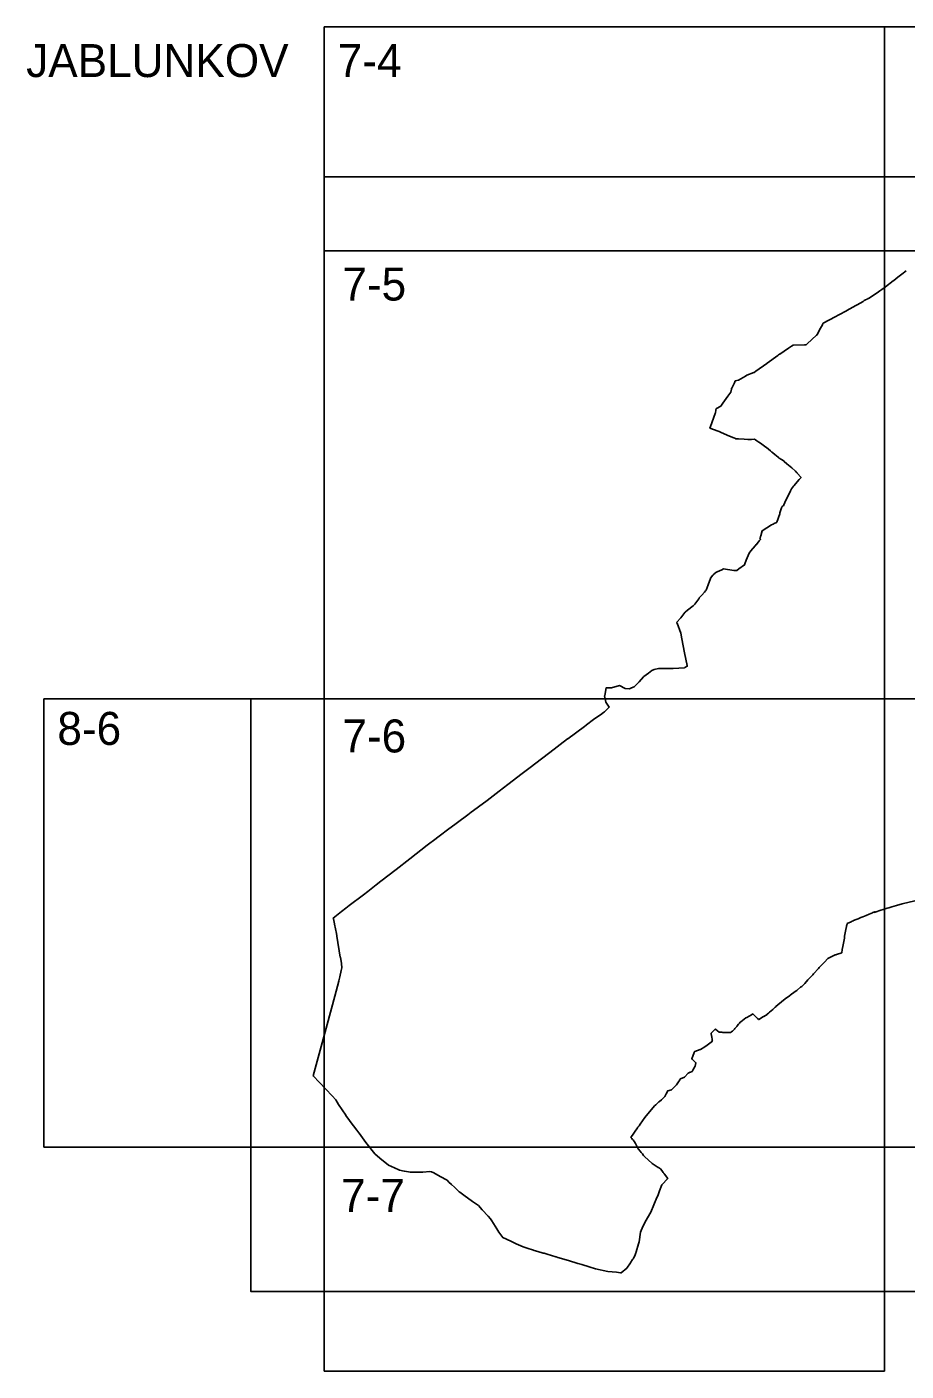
# Model space of a CAD drawing. Extents: x -447352 to -425530, y -1135906 to -1125104.
# Drawn here: x -438504.6 to -438259.4, y -1126653.4 to -1126278.4 of the extents above; entities that cross this region are included whole.
import ezdxf

# ---------------------------------------------------------------- set-up
doc = ezdxf.new("R2010")
doc.units = 0
for name, color, linetype in [('Vrstva 1', 7, 'Continuous'), ('Vrstva 10', 7, 'Continuous'), ('Vrstva 4', 7, 'Continuous')]:
    doc.layers.add(name, color=color, linetype=linetype)

msp = doc.modelspace()

# ---------------------------------------------------------------- linework, layer by layer
at = {"layer": 'Vrstva 1'}
for points in [[(-438259.36, -1126346.44), (-438260.57, -1126347.4), (-438260.57, -1126347.4), (-438261.72, -1126348.27), (-438262.29, -1126348.7), (-438262.87, -1126349.14), (-438263.03, -1126349.26), (-438265.16, -1126350.9), (-438266.23, -1126351.72), (-438266.7, -1126352.06), (-438267.46, -1126352.57), (-438267.71, -1126352.73), (-438268.3, -1126353.12), (-438268.34, -1126353.15), (-438268.55, -1126353.29), (-438269.46, -1126353.89), (-438269.47, -1126353.89), (-438269.94, -1126354.15), (-438270.09, -1126354.23), (-438270.27, -1126354.33), (-438270.73, -1126354.58), (-438270.91, -1126354.69), (-438271.07, -1126354.78), (-438271.17, -1126354.84), (-438271.41, -1126354.98), (-438273.07, -1126355.92), (-438273.24, -1126356.01), (-438273.47, -1126356.14), (-438275.94, -1126357.54), (-438276.06, -1126357.61), (-438278.17, -1126358.74), (-438279.19, -1126359.29), (-438282.53, -1126361.1), (-438282.7, -1126361.4), (-438282.76, -1126361.51), (-438283.54, -1126362.97), (-438284.22, -1126364.29), (-438284.36, -1126364.42), (-438284.45, -1126364.5), (-438285.59, -1126365.54), (-438287.1, -1126366.92), (-438287.27, -1126367.07), (-438287.27, -1126367.08), (-438287.74, -1126367.09), (-438290.93, -1126367.18), (-438290.94, -1126367.18), (-438291.37, -1126367.47), (-438292.2, -1126368.04), (-438294.67, -1126369.7), (-438294.71, -1126369.72), (-438294.95, -1126369.9), (-438295.22, -1126370.1), (-438298.2, -1126372.23), (-438298.27, -1126372.28), (-438301.27, -1126374.46), (-438301.74, -1126374.8), (-438301.9, -1126374.86), (-438303.84, -1126375.58), (-438303.85, -1126375.58), (-438304.24, -1126375.82), (-438306.12, -1126376.98), (-438307.04, -1126377.19), (-438307.29, -1126377.7), (-438308.05, -1126379.21), (-438308.06, -1126379.22), (-438308.13, -1126379.48), (-438308.33, -1126380.32), (-438309.16, -1126381.43), (-438310.53, -1126383.38), (-438311.09, -1126384.19), (-438311.12, -1126384.21), (-438312.28, -1126384.85), (-438312.38, -1126384.91), (-438312.45, -1126385.3), (-438312.6, -1126386.11), (-438312.65, -1126386.3), (-438313.94, -1126389.88), (-438314.11, -1126390.36), (-438314.08, -1126390.35), (-438314.06, -1126390.34), (-438313.38, -1126390.6), (-438311.57, -1126391.26), (-438310.95, -1126391.55), (-438308.66, -1126392.63), (-438308.64, -1126392.63), (-438307.48, -1126393.1), (-438307.01, -1126393.28), (-438306.98, -1126393.29), (-438306.55, -1126393.32), (-438306.41, -1126393.33), (-438306.19, -1126393.35), (-438304.59, -1126393.45), (-438303.55, -1126393.52), (-438302.5, -1126393.49), (-438301.66, -1126393.46), (-438301.65, -1126393.46), (-438301.37, -1126393.61), (-438301, -1126393.87), (-438300.45, -1126394.25), (-438300.06, -1126394.53), (-438298.5, -1126395.67), (-438298.33, -1126395.79), (-438297.22, -1126396.71), (-438296.83, -1126397.03), (-438296.65, -1126397.18), (-438295.9, -1126397.79), (-438295.63, -1126398.02), (-438295.03, -1126398.51), (-438294.81, -1126398.69), (-438294.17, -1126399.11), (-438293.42, -1126399.61), (-438293.39, -1126399.63), (-438292.63, -1126400.31), (-438291.75, -1126401.09), (-438291.31, -1126401.47), (-438290.3, -1126402.36), (-438290.04, -1126402.59), (-438289.99, -1126402.64), (-438289.89, -1126402.74), (-438289.88, -1126402.75), (-438289.79, -1126402.85), (-438289.76, -1126402.88), (-438288.71, -1126404.11), (-438288.72, -1126404.12), (-438289.16, -1126404.61), (-438289.22, -1126404.68), (-438289.79, -1126405.31), (-438290.61, -1126406.37), (-438290.78, -1126406.58), (-438291.34, -1126407.3), (-438291.64, -1126407.83), (-438291.66, -1126407.87), (-438291.67, -1126407.89), (-438291.8, -1126408.17), (-438292.6, -1126409.84), (-438292.91, -1126410.48), (-438293.53, -1126411.77), (-438293.64, -1126412.01), (-438293.65, -1126412.01), (-438293.69, -1126412.04), (-438293.98, -1126412.24), (-438294.06, -1126412.28), (-438294.11, -1126412.38), (-438294.2, -1126412.58), (-438294.29, -1126412.86), (-438294.46, -1126413.42), (-438294.47, -1126413.44), (-438294.59, -1126413.94), (-438294.61, -1126414.01), (-438294.6, -1126414.07), (-438294.59, -1126414.15), (-438294.59, -1126414.22), (-438294.6, -1126414.27), (-438295.48, -1126416.6), (-438295.5, -1126416.65), (-438295.52, -1126416.69), (-438295.53, -1126416.7), (-438296.23, -1126417), (-438296.48, -1126417.11), (-438296.95, -1126417.35), (-438299.56, -1126419.04), (-438299.56, -1126419.04), (-438299.93, -1126420.35), (-438300.01, -1126420.61), (-438300.12, -1126421.03), (-438300.18, -1126421.24), (-438300.18, -1126421.25), (-438300.17, -1126421.25), (-438300, -1126421.41), (-438300.01, -1126421.42), (-438300.37, -1126421.81), (-438301.17, -1126422.81), (-438301.18, -1126422.82), (-438301.39, -1126423.07), (-438301.39, -1126423.08), (-438301.51, -1126423.23), (-438302.67, -1126424.58), (-438303.21, -1126425.21), (-438303.97, -1126427.16), (-438304.35, -1126428.18), (-438304.48, -1126428.53), (-438306.01, -1126429.63), (-438306.63, -1126430.07), (-438306.81, -1126430.11), (-438306.83, -1126430.11), (-438307.46, -1126430.02), (-438310.3, -1126429.6), (-438310.79, -1126429.84), (-438312.12, -1126430.48), (-438312.66, -1126430.74), (-438312.69, -1126430.77), (-438313.12, -1126431.18), (-438313.29, -1126431.4), (-438313.95, -1126432.25), (-438313.95, -1126432.26), (-438314.62, -1126434.06), (-438315.19, -1126435.56), (-438315.19, -1126435.56), (-438315.33, -1126435.78), (-438315.66, -1126436.15), (-438316.38, -1126436.95), (-438317.08, -1126437.72), (-438317.09, -1126437.74), (-438317.22, -1126437.93), (-438318.29, -1126439.5), (-438318.76, -1126439.88), (-438320.33, -1126441.14), (-438321, -1126441.68), (-438321.1, -1126441.76), (-438321.13, -1126441.8), (-438322.25, -1126443.23), (-438323.39, -1126444.54), (-438323.24, -1126444.71), (-438323.23, -1126444.74), (-438323.23, -1126444.75), (-438322.22, -1126447.51), (-438321.94, -1126449.17), (-438321.62, -1126451.12), (-438321.21, -1126453.08), (-438320.48, -1126456.58), (-438320.44, -1126456.78), (-438321.09, -1126457.12), (-438321.21, -1126457.19), (-438324.38, -1126457.45), (-438324.54, -1126457.45), (-438326.03, -1126457.42), (-438328.42, -1126457.4), (-438329.7, -1126457.67), (-438330.3, -1126457.94), (-438331.28, -1126458.74), (-438332.58, -1126459.61), (-438332.67, -1126459.72), (-438333.83, -1126461.14), (-438335.28, -1126462.48), (-438335.97, -1126462.8), (-438336.57, -1126463.08), (-438337.74, -1126463.01), (-438339.35, -1126462.16), (-438341.59, -1126462.83), (-438343.07, -1126462.8), (-438343.45, -1126464.91), (-438343.46, -1126464.93), (-438343.47, -1126465.02), (-438343.18, -1126466.83), (-438342.21, -1126468.15), (-438342.2, -1126468.17), (-438342.94, -1126468.92), (-438343.55, -1126469.48), (-438343.8, -1126469.71), (-438344.6, -1126470.34), (-438346.53, -1126471.57), (-438346.59, -1126471.61), (-438348.56, -1126473.14), (-438348.62, -1126473.18), (-438349.11, -1126473.56), (-438353.77, -1126477.02), (-438353.8, -1126477.05), (-438358.75, -1126480.81), (-438363.01, -1126484.06), (-438363.89, -1126484.72), (-438366.46, -1126486.66), (-438370.46, -1126489.79), (-438372.9, -1126491.66), (-438376.21, -1126494.19), (-438376.26, -1126494.23), (-438381.05, -1126497.74), (-438381.28, -1126497.92), (-438384.89, -1126500.6), (-438387.28, -1126502.42), (-438389.25, -1126503.9), (-438391.57, -1126505.65), (-438391.8, -1126505.82), (-438392.93, -1126506.71), (-438397.75, -1126510.51), (-438401.64, -1126513.46), (-438405.86, -1126516.71), (-438407.15, -1126517.71), (-438409.54, -1126519.59), (-438410.72, -1126520.51), (-438414.66, -1126523.56), (-438415.59, -1126524.27), (-438416.83, -1126525.23), (-438419.15, -1126527.03), (-438419.15, -1126527.03), (-438419.11, -1126527.21), (-438418.82, -1126528.59), (-438418.79, -1126528.75), (-438418.26, -1126531.29), (-438418.1, -1126532.02), (-438418.1, -1126532.06), (-438417.17, -1126537.94), (-438417.16, -1126537.97), (-438416.86, -1126539.7), (-438416.86, -1126539.72), (-438416.8, -1126540.09), (-438416.74, -1126540.51), (-438416.77, -1126540.88), (-438416.92, -1126541.61), (-438417.3, -1126543.4), (-438417.59, -1126544.58), (-438417.61, -1126544.63), (-438418.72, -1126548.8), (-438420.82, -1126556.68), (-438422.81, -1126563.9), (-438424.74, -1126571), (-438424.75, -1126571.04), (-438419.47, -1126576.64), (-438418.42, -1126577.77), (-438417.66, -1126578.99), (-438415.64, -1126582.05), (-438415.59, -1126582.12), (-438414.58, -1126583.53), (-438414.42, -1126583.74), (-438412.54, -1126586.22), (-438411.97, -1126586.96), (-438411.94, -1126587), (-438411.42, -1126587.72), (-438410.04, -1126589.62), (-438409.71, -1126590.07), (-438407.56, -1126592.79), (-438406.16, -1126594.01), (-438403.76, -1126595.99), (-438402.02, -1126596.74), (-438400.83, -1126597.26), (-438400.7, -1126597.31), (-438399.37, -1126597.59), (-438399.23, -1126597.62), (-438397.61, -1126597.95), (-438397.58, -1126597.95), (-438396.62, -1126597.93), (-438396.24, -1126597.93), (-438395.72, -1126597.92), (-438395.04, -1126597.91), (-438394.13, -1126597.87), (-438392.18, -1126597.71), (-438391.73, -1126597.78), (-438391.07, -1126598.13), (-438389.35, -1126599.08), (-438387.39, -1126600.18), (-438386.87, -1126600.66), (-438386.15, -1126601.34), (-438385.35, -1126602.09), (-438384.03, -1126603.39), (-438383.89, -1126603.49), (-438382.7, -1126604.34), (-438380.29, -1126606.05), (-438378.65, -1126607.23), (-438377.6, -1126608.41), (-438375.96, -1126610.23), (-438375.32, -1126610.94), (-438374.96, -1126611.53), (-438374.5, -1126612.27), (-438373.56, -1126613.74), (-438372.93, -1126614.66), (-438371.89, -1126616.1), (-438370.82, -1126616.61), (-438369.44, -1126617.26), (-438368.13, -1126617.87), (-438366.16, -1126618.76), (-438365.03, -1126619.11), (-438363.31, -1126619.68), (-438363.16, -1126619.73), (-438362.07, -1126620.05), (-438360.65, -1126620.47), (-438360.64, -1126620.47), (-438360.43, -1126620.53), (-438360.37, -1126620.55), (-438359.51, -1126620.81), (-438357.12, -1126621.5), (-438357, -1126621.54), (-438356.52, -1126621.68), (-438353.59, -1126622.55), (-438350.9, -1126623.38), (-438350.56, -1126623.48), (-438349.8, -1126623.71), (-438347.79, -1126624.33), (-438346.06, -1126624.88), (-438342.6, -1126625.62)], [(-438342.6, -1126625.62), (-438340.21, -1126625.81), (-438339.01, -1126626.04), (-438338.9, -1126625.95), (-438337.32, -1126624.68), (-438336.29, -1126623.2), (-438336.18, -1126623.05), (-438335.66, -1126622.29), (-438335.55, -1126622.12), (-438335.41, -1126621.89), (-438335.03, -1126621.26), (-438334.76, -1126620.43), (-438334.74, -1126620.36), (-438334.72, -1126620.31), (-438334.69, -1126620.2), (-438334.66, -1126620.11), (-438334.66, -1126620.1), (-438334.03, -1126617.9), (-438333.89, -1126617.38), (-438333.44, -1126614.63), (-438333.44, -1126614.63), (-438333.25, -1126614.19), (-438332.99, -1126613.57), (-438332.2, -1126611.74), (-438330.63, -1126609.09), (-438328.88, -1126604.96), (-438328.56, -1126604.32), (-438328.52, -1126604.19), (-438328.13, -1126603.09), (-438327.54, -1126601.42), (-438325.86, -1126599.71), (-438326.79, -1126598.47), (-438326.85, -1126598.38), (-438326.9, -1126598.32), (-438326.93, -1126598.28), (-438327, -1126598.18), (-438327.05, -1126598.1), (-438327.13, -1126597.98), (-438327.49, -1126597.46), (-438327.86, -1126597), (-438328.43, -1126596.63), (-438328.53, -1126596.57), (-438330.18, -1126595.5), (-438332.37, -1126593.56), (-438332.5, -1126593.39), (-438332.53, -1126593.35), (-438332.61, -1126593.25), (-438332.95, -1126592.83), (-438333.28, -1126592.42), (-438333.54, -1126592.1), (-438334.02, -1126591.51), (-438334.1, -1126591.41), (-438334.6, -1126590.45), (-438334.89, -1126589.89), (-438335.12, -1126589.46), (-438335.17, -1126589.37), (-438335.21, -1126589.32), (-438335.47, -1126589.03), (-438335.67, -1126588.8), (-438335.93, -1126588.51), (-438336.15, -1126588.26), (-438334.29, -1126585.52), (-438334.2, -1126585.4), (-438333.88, -1126584.95), (-438333.56, -1126584.51), (-438332.23, -1126582.68), (-438329.55, -1126579.42), (-438329.2, -1126579.1), (-438328.49, -1126578.4), (-438328.38, -1126578.31), (-438328.19, -1126578.17), (-438327.59, -1126577.69), (-438326.73, -1126576.85), (-438326.32, -1126576.09), (-438325.85, -1126575.22), (-438324.8, -1126574.98), (-438323.4, -1126573.55), (-438322.86, -1126572.7), (-438322.85, -1126572.69), (-438322.85, -1126572.67), (-438322.64, -1126572.34), (-438322.59, -1126572.26), (-438322.35, -1126571.87), (-438321.19, -1126571.43), (-438320.17, -1126570.25), (-438319.64, -1126570.05), (-438319.52, -1126570), (-438319.1, -1126569.84), (-438318.88, -1126569.45), (-438318.83, -1126569.36), (-438318.66, -1126569.06), (-438318.25, -1126568.32), (-438318.05, -1126567.41), (-438318.05, -1126567.39), (-438318.04, -1126567.38), (-438319.09, -1126566.39), (-438319.11, -1126566.38), (-438319.12, -1126566.36), (-438319.17, -1126566.32), (-438318.52, -1126564.52), (-438318.45, -1126564.32), (-438318.29, -1126564.26), (-438317.56, -1126563.97), (-438316.87, -1126563.7), (-438316.75, -1126563.65), (-438315.54, -1126562.94), (-438315.42, -1126562.86), (-438315.42, -1126562.86), (-438315.41, -1126562.85), (-438315.29, -1126562.78), (-438313.43, -1126561.38), (-438313.43, -1126561.34), (-438313.46, -1126561.18), (-438313.53, -1126560.7), (-438313.59, -1126560.35), (-438313.69, -1126559.73), (-438313.71, -1126559.62), (-438313.73, -1126559.49), (-438313.75, -1126559.32), (-438313.78, -1126559.18), (-438313.24, -1126558.62), (-438312.68, -1126558.05), (-438312.64, -1126558), (-438312.5, -1126558.1), (-438311.5, -1126558.89), (-438310.82, -1126558.9), (-438310.76, -1126558.9), (-438310.51, -1126558.91), (-438310.35, -1126558.91), (-438309.04, -1126558.93), (-438308.41, -1126558.95), (-438308.14, -1126558.79), (-438308.11, -1126558.77), (-438307.99, -1126558.7), (-438307.85, -1126558.61), (-438307.81, -1126558.58), (-438307.27, -1126557.98), (-438307.16, -1126557.86), (-438307.07, -1126557.76), (-438306.9, -1126557.58), (-438306.82, -1126557.49), (-438306.71, -1126557.37), (-438306.68, -1126557.33), (-438306.65, -1126557.3), (-438306.6, -1126557.24), (-438306.51, -1126557.13), (-438306.11, -1126556.63), (-438305.9, -1126556.37), (-438305.65, -1126556.05), (-438305.54, -1126555.97), (-438304.08, -1126554.9), (-438303.87, -1126554.77), (-438302.51, -1126554), (-438302.11, -1126553.77), (-438302.11, -1126553.77), (-438301.97, -1126553.92), (-438301.26, -1126554.63), (-438300.89, -1126555.01), (-438300.71, -1126555.18), (-438300.56, -1126555.33), (-438300.47, -1126555.29), (-438299.19, -1126554.52), (-438299.1, -1126554.47), (-438298.17, -1126553.91), (-438298.13, -1126553.88), (-438297.8, -1126553.59), (-438297.75, -1126553.55), (-438297.58, -1126553.4), (-438297.57, -1126553.39), (-438297.57, -1126553.39), (-438297.53, -1126553.35), (-438297.49, -1126553.31), (-438296.6, -1126552.5), (-438296.58, -1126552.49), (-438295.99, -1126551.95), (-438295.88, -1126551.86), (-438295.77, -1126551.76), (-438295.77, -1126551.76), (-438295.76, -1126551.76), (-438295.76, -1126551.76), (-438295.76, -1126551.75), (-438295.75, -1126551.75), (-438295.74, -1126551.74), (-438295.74, -1126551.74), (-438295.73, -1126551.73), (-438295.73, -1126551.73), (-438295.72, -1126551.73), (-438295.72, -1126551.73), (-438295.14, -1126551.24), (-438293.15, -1126549.56), (-438291.95, -1126548.71), (-438291.83, -1126548.63), (-438291.78, -1126548.59), (-438291.76, -1126548.58), (-438291.71, -1126548.55), (-438291.35, -1126548.28), (-438290.11, -1126547.34), (-438289.93, -1126547.2), (-438289.72, -1126547.04), (-438289.7, -1126547.02), (-438288.82, -1126546.35), (-438288.47, -1126546.08), (-438288.42, -1126546.02), (-438288.33, -1126545.92), (-438287.69, -1126545.24), (-438286.79, -1126544.26), (-438285.43, -1126542.85), (-438285.21, -1126542.62), (-438284.96, -1126542.34), (-438284.12, -1126541.39), (-438283.83, -1126541.07), (-438283.63, -1126540.86), (-438283.34, -1126540.54), (-438282.16, -1126539.35), (-438281.23, -1126538.33), (-438279.17, -1126537.32), (-438279.01, -1126537.27), (-438278.81, -1126537.19), (-438277.37, -1126536.7), (-438277.22, -1126535.83), (-438277.06, -1126534.96), (-438276.64, -1126532.59), (-438276.56, -1126532.12), (-438276.23, -1126530.24), (-438276.03, -1126529.36), (-438276, -1126529.24), (-438275.95, -1126529.05), (-438275.94, -1126529.01), (-438275.92, -1126528.94), (-438275.91, -1126528.9), (-438275.9, -1126528.85), (-438275.89, -1126528.81), (-438275.88, -1126528.79), (-438275.82, -1126528.58), (-438274.74, -1126528.04), (-438274.45, -1126527.9), (-438274.43, -1126527.89), (-438274.18, -1126527.76), (-438274.13, -1126527.74), (-438272.36, -1126527.02), (-438272.33, -1126527.01), (-438272.3, -1126526.99), (-438271.5, -1126526.68), (-438270.54, -1126526.28), (-438269.73, -1126525.94), (-438268.79, -1126525.55), (-438268.71, -1126525.52), (-438268.1, -1126525.28), (-438268.25, -1126525.44), (-438268.01, -1126525.35), (-438267.52, -1126525.15), (-438266.99, -1126524.99), (-438265.29, -1126524.47), (-438264.7, -1126524.3), (-438264.25, -1126524.18), (-438263.36, -1126523.93), (-438262.05, -1126523.55), (-438260.51, -1126523.09), (-438256.97, -1126522.22)]]:
    msp.add_lwpolyline(points, dxfattribs=at)
at = {"layer": 'Vrstva 10'}
msp.add_lwpolyline([(-438109.21, -1126320.23), (-438109.21, -1126631.21), (-438442.08, -1126631.21), (-438442.08, -1126465.91), (-438421.71, -1126465.91), (-438421.71, -1126340.91), (-438421.71, -1126320.23), (-438109.21, -1126320.23)], dxfattribs=at)
at = {"layer": 'Vrstva 4'}
for p, q in [((-438421.71, -1126278.41), (-438109.21, -1126278.41)), ((-438499.84, -1126465.91), (-438499.84, -1126590.91)), ((-438421.71, -1126653.41), (-438265.46, -1126653.41))]:
    msp.add_line(p, q, dxfattribs=at)
for points in [[(-438265.46, -1126278.41), (-438265.46, -1126340.91), (-438421.71, -1126340.91), (-438421.71, -1126278.41)], [(-438109.21, -1126278.41), (-438109.21, -1126340.91), (-438265.46, -1126340.91), (-438265.46, -1126278.41)], [(-438499.84, -1126465.91), (-438421.71, -1126465.91), (-438421.71, -1126590.91), (-438499.84, -1126590.91)], [(-438421.71, -1126653.41), (-438421.71, -1126590.91), (-438265.46, -1126590.91), (-438265.46, -1126653.41)]]:
    msp.add_lwpolyline(points, dxfattribs=at)
for points in [[(-438265.46, -1126340.91), (-438265.46, -1126465.91), (-438421.71, -1126465.91), (-438421.71, -1126340.91)], [(-438109.21, -1126340.91), (-438109.21, -1126465.91), (-438265.46, -1126465.91), (-438265.46, -1126340.91)], [(-438265.46, -1126465.91), (-438265.46, -1126590.91), (-438421.71, -1126590.91), (-438421.71, -1126465.91)], [(-438109.21, -1126465.91), (-438109.21, -1126590.91), (-438265.46, -1126590.91), (-438265.46, -1126465.91)]]:
    msp.add_lwpolyline(points, close=True, dxfattribs=at)

# ---------------------------------------------------------------- texts
at = {"layer": 'Vrstva 1'}
for s, p in [('JABLUNKOV', (-438504.75, -1126292.41)), ('7-4', (-438417.9, -1126292.41)), ('7-5', (-438416.59, -1126354.75)), ('8-6', (-438496.06, -1126478.72)), ('7-6', (-438416.59, -1126480.82)), ('7-7', (-438416.95, -1126608.99))]:
    msp.add_text(s, height=9.2, dxfattribs=at).set_placement(p)

doc.saveas('drawing.dxf')
